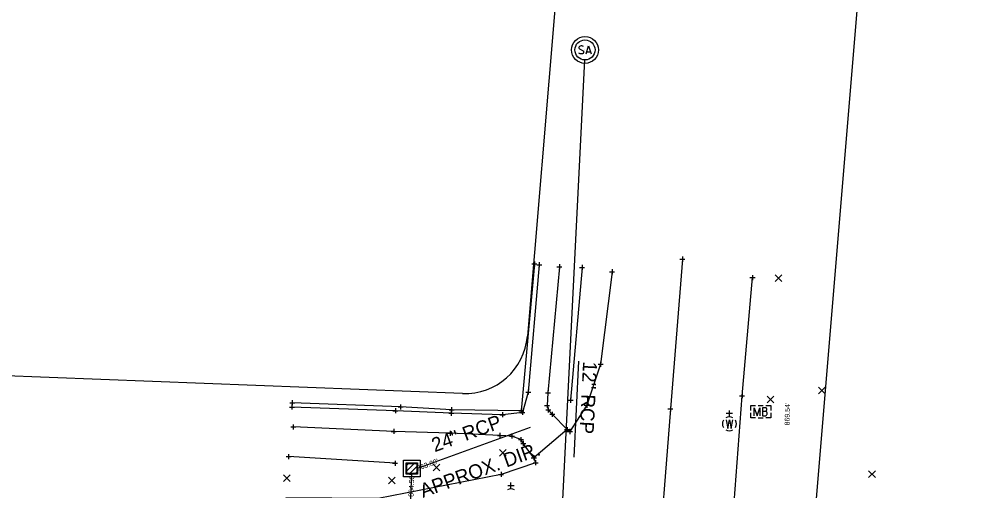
# Model space of a CAD drawing. Extents: x 1380550 to 1381945, y 468927 to 470496.
# Drawn here: x 1381495.3 to 1381685.3, y 470278.1 to 470372 of the extents above; entities that cross this region are included whole.
import ezdxf

# ---------------------------------------------------------------- set-up
doc = ezdxf.new("R2010")
doc.units = 0
for name, color, linetype in [('DR_X_Cells', 7, 'Continuous'), ('DR_X_Ditch', 7, 'Continuous'), ('DR_X_Storm_Sewer', 7, 'Continuous'), ('DR_X_Text', 7, 'Continuous'), ('GK_Drainage_Nodes', 7, 'Continuous'), ('PV_X_COP', 7, 'Continuous'), ('PV_X_EOP', 7, 'Continuous'), ('PV_X_Walk', 7, 'Continuous'), ('RD_X_Cells', 7, 'Continuous'), ('RD_X_Fence', 7, 'Continuous'), ('RW_X_Esmt_General', 7, 'Continuous'), ('SC_Scratch1', 7, 'Continuous'), ('SV_X_Random_Point', 7, 'Continuous'), ('SV_X_Shot_Marker', 7, 'Continuous'), ('UT_X_Sanitary_Cells', 7, 'Continuous'), ('UT_X_Sanitary_Line', 7, 'Continuous'), ('UT_X_Sanitary_Text', 7, 'Continuous'), ('UT_X_Water_Cells', 7, 'Continuous')]:
    doc.layers.add(name, color=color, linetype=linetype)

msp = doc.modelspace()

# ---------------------------------------------------------------- linework, layer by layer
at = {"layer": 'DR_X_Cells'}
for p, q in [((1381572.37, 470281.94), (1381574.13, 470283.7)), ((1381572.37, 470283.07), (1381573, 470283.7)), ((1381572.97, 470281.41), (1381574.66, 470283.1)), ((1381574.1, 470281.41), (1381574.66, 470281.97))]:
    msp.add_line(p, q, dxfattribs=at)
for points in [[(1381571.85, 470284.22), (1381575.18, 470284.22), (1381575.18, 470280.89), (1381571.85, 470280.89)], [(1381572.37, 470283.7), (1381574.66, 470283.7), (1381574.66, 470281.41), (1381572.37, 470281.41)], [(1381572.52, 470283.56), (1381574.51, 470283.56), (1381574.51, 470281.56), (1381572.52, 470281.56)]]:
    msp.add_lwpolyline(points, close=True, dxfattribs=at)
at = {"layer": 'DR_X_Ditch'}
for points in [[(1381607.42, 470322.6), (1381605.14, 470296.15)], [(1381570.18, 470283.61), (1381548.95, 470284.92)]]:
    msp.add_lwpolyline(points, dxfattribs=at)
at = {"layer": 'DR_X_Storm_Sewer'}
for p, q in [((1381574.51, 470282.56), (1381597.14, 470290.77)), ((1381572.17, 470247.58), (1381573.51, 470281.56))]:
    msp.add_line(p, q, dxfattribs=at)
at = {"layer": 'DR_X_Text'}
msp.add_line((1381605.85, 470284.84), (1381606.8, 470303.9), dxfattribs=at)
at = {"layer": 'GK_Drainage_Nodes'}
for p, q in [((1381608, 470367.88), (1381608, 470367.88)), ((1381608, 470365.88), (1381608, 470365.88)), ((1381608, 470365.88), (1381608, 470365.88)), ((1381608, 470365.88), (1381608, 470365.88)), ((1381608, 470363.88), (1381608, 470363.88)), ((1381573.51, 470284.22), (1381573.51, 470284.22)), ((1381572.52, 470282.56), (1381572.52, 470282.56)), ((1381573.51, 470283.56), (1381573.51, 470283.56)), ((1381573.51, 470282.56), (1381573.51, 470282.56)), ((1381573.51, 470282.56), (1381573.51, 470282.56)), ((1381573.51, 470282.56), (1381573.51, 470282.56)), ((1381574.51, 470282.56), (1381574.51, 470282.56)), ((1381573.51, 470281.56), (1381573.51, 470281.56)), ((1381573.51, 470280.89), (1381573.51, 470280.89))]:
    msp.add_line(p, q, dxfattribs=at)
msp.add_circle((1381608, 470365.88), 2, dxfattribs=at)
at = {"layer": 'PV_X_COP'}
msp.add_lwpolyline([(1381627.41, 470324.23), (1381625.02, 470294.42), (1381622.34, 470259.95), (1381618.76, 470220.14), (1381616.92, 470200.19), (1381615.1, 470178.83), (1381610.95, 470124.78), (1381606.49, 470071.23), (1381602.26, 470019.36), (1381598.18, 469969.8), (1381595.01, 469928.06), (1381590.91, 469878.81), (1381589.36, 469859.11), (1381585.99, 469815.58), (1381581.29, 469760.78)], dxfattribs=at)
at = {"layer": 'PV_X_EOP'}
for points in [[(1381613.39, 470321.73), (1381611.1, 470303.3), (1381608.36, 470295.15), (1381605.01, 470289.92), (1381604.44, 470290.29), (1381597.81, 470284.69), (1381598.17, 470283.7), (1381591.29, 470281.39), (1381566.82, 470276.57), (1381548.39, 470276.73)], [(1381677.82, 470243.96), (1381667.49, 470244.25), (1381661.32, 470244.63), (1381647.84, 470248.5), (1381643.91, 470251.15), (1381641.09, 470253.81), (1381638.63, 470258.08), (1381637.55, 470273.11), (1381639.29, 470297.03), (1381641.37, 470320.57)]]:
    msp.add_lwpolyline(points, dxfattribs=at)
at = {"layer": 'PV_X_Walk'}
for points in [[(1381598.9, 470323.13), (1381596.7, 470297.78), (1381595.54, 470293.73), (1381591.57, 470293.27), (1381581.37, 470293.57), (1381570.24, 470294.06), (1381549.62, 470294.77)], [(1381602.92, 470322.73), (1381600.62, 470297.61), (1381600.44, 470295.13), (1381600.68, 470294.22), (1381601.47, 470293.36), (1381604.44, 470290.29), (1381597.81, 470284.69), (1381595.69, 470287.54), (1381595.24, 470288.31), (1381593.46, 470289.01), (1381591.05, 470289.15), (1381581.13, 470289.58), (1381569.91, 470289.93), (1381549.88, 470290.83)]]:
    msp.add_lwpolyline(points, dxfattribs=at)
at = {"layer": 'RD_X_Cells'}
for p, q in [((1381642.49, 470295.09), (1381643.5, 470295.09)), ((1381643.01, 470293.86), (1381643.01, 470293.86)), ((1381642.49, 470292.64), (1381643.5, 470292.64))]:
    msp.add_line(p, q, dxfattribs=at)
for points in [[(1381641.01, 470294.12), (1381641.01, 470295.09), (1381641.98, 470295.09)], [(1381644.01, 470295.09), (1381645.01, 470295.09), (1381645.01, 470294.12)], [(1381641.98, 470292.64), (1381641.01, 470292.64), (1381641.01, 470293.61)], [(1381641.71, 470293.06), (1381641.71, 470294.66), (1381642.29, 470293.06), (1381642.84, 470294.66), (1381642.84, 470293.06)], [(1381644.03, 470293.93), (1381644.09, 470294), (1381644.13, 470294.03), (1381644.15, 470294.07), (1381644.17, 470294.1), (1381644.19, 470294.15), (1381644.2, 470294.19), (1381644.23, 470294.27), (1381644.23, 470294.31), (1381644.23, 470294.36), (1381644.22, 470294.44), (1381644.19, 470294.5), (1381644.15, 470294.55), (1381644.09, 470294.6), (1381644.04, 470294.63), (1381644.02, 470294.64), (1381643.95, 470294.66), (1381643.33, 470294.66), (1381643.33, 470293.06), (1381644.03, 470293.06), (1381644.12, 470293.11), (1381644.19, 470293.18), (1381644.25, 470293.28), (1381644.29, 470293.39), (1381644.3, 470293.51), (1381644.3, 470293.58), (1381644.28, 470293.66), (1381644.23, 470293.77), (1381644.17, 470293.85), (1381644.03, 470293.93), (1381643.33, 470293.93)], [(1381645.01, 470293.61), (1381645.01, 470292.64), (1381644.01, 470292.64)]]:
    msp.add_lwpolyline(points, dxfattribs=at)
at = {"layer": 'RD_X_Fence'}
msp.add_lwpolyline([(1381597.94, 470323.28), (1381595.32, 470294.01), (1381581.44, 470294.24), (1381571.27, 470294.81), (1381549.69, 470295.66)], dxfattribs=at)
at = {"layer": 'RW_X_Esmt_General'}
for p, q in [((1381612.2, 470496.45), (1381596.54, 470308.93)), ((1381583.6, 470297.48), (1380561.01, 470336.99))]:
    msp.add_line(p, q, dxfattribs=at)
msp.add_lwpolyline([(1381668.02, 470443.9), (1381652.43, 470257.4), (1381784.26, 470253.87)], dxfattribs=at)
msp.add_arc((1381584.08, 470309.97), 12.5, 267.7876, 355.2253, dxfattribs=at)
at = {"layer": 'SV_X_Random_Point'}
for p, q in [((1381645.91, 470319.77), (1381647.24, 470321.1)), ((1381645.91, 470321.1), (1381647.24, 470319.77)), ((1381654.52, 470297.42), (1381655.86, 470298.76)), ((1381654.52, 470298.76), (1381655.86, 470297.42)), ((1381644.26, 470295.6), (1381645.6, 470296.93)), ((1381644.26, 470296.93), (1381645.6, 470295.6)), ((1381590.99, 470284.99), (1381592.32, 470286.32)), ((1381590.99, 470286.32), (1381592.32, 470284.99)), ((1381577.75, 470282.09), (1381579.09, 470283.42)), ((1381577.75, 470283.42), (1381579.09, 470282.09)), ((1381664.51, 470280.76), (1381665.85, 470282.1)), ((1381664.51, 470282.1), (1381665.85, 470280.76)), ((1381547.97, 470279.98), (1381549.3, 470281.31)), ((1381547.97, 470281.31), (1381549.3, 470279.98)), ((1381568.86, 470279.49), (1381570.2, 470280.83)), ((1381568.86, 470280.83), (1381570.2, 470279.49))]:
    msp.add_line(p, q, dxfattribs=at)
at = {"layer": 'SV_X_Shot_Marker'}
for p, q in [((1381597.94, 470323.78), (1381597.94, 470322.78)), ((1381598.9, 470323.63), (1381598.9, 470322.63)), ((1381626.91, 470324.23), (1381627.91, 470324.23)), ((1381627.41, 470324.73), (1381627.41, 470323.73)), ((1381627.41, 470324.23), (1381627.41, 470324.23)), ((1381597.44, 470323.28), (1381598.44, 470323.28)), ((1381597.94, 470323.28), (1381597.94, 470323.28)), ((1381598.4, 470323.13), (1381599.4, 470323.13)), ((1381598.9, 470323.13), (1381598.9, 470323.13)), ((1381602.42, 470322.73), (1381603.42, 470322.73)), ((1381602.92, 470323.23), (1381602.92, 470322.23)), ((1381602.92, 470322.73), (1381602.92, 470322.73)), ((1381606.92, 470322.6), (1381607.92, 470322.6)), ((1381607.42, 470323.1), (1381607.42, 470322.1)), ((1381607.42, 470322.6), (1381607.42, 470322.6)), ((1381612.89, 470321.73), (1381613.89, 470321.73)), ((1381613.39, 470322.23), (1381613.39, 470321.23)), ((1381613.39, 470321.73), (1381613.39, 470321.73)), ((1381640.87, 470320.57), (1381641.87, 470320.57)), ((1381641.37, 470321.07), (1381641.37, 470320.07)), ((1381641.37, 470320.57), (1381641.37, 470320.57)), ((1381610.6, 470303.3), (1381611.6, 470303.3)), ((1381610.6, 470303.3), (1381611.6, 470303.3)), ((1381611.1, 470303.8), (1381611.1, 470302.8)), ((1381611.1, 470303.8), (1381611.1, 470302.8)), ((1381611.1, 470303.3), (1381611.1, 470303.3)), ((1381611.1, 470303.3), (1381611.1, 470303.3)), ((1381596.2, 470297.78), (1381597.2, 470297.78)), ((1381596.2, 470297.78), (1381597.2, 470297.78)), ((1381596.7, 470298.28), (1381596.7, 470297.28)), ((1381596.7, 470298.28), (1381596.7, 470297.28)), ((1381596.7, 470297.78), (1381596.7, 470297.78)), ((1381596.7, 470297.78), (1381596.7, 470297.78)), ((1381600.12, 470297.61), (1381601.12, 470297.61)), ((1381600.62, 470298.11), (1381600.62, 470297.11)), ((1381600.62, 470297.61), (1381600.62, 470297.61)), ((1381638.79, 470297.03), (1381639.79, 470297.03)), ((1381639.29, 470297.53), (1381639.29, 470296.53)), ((1381639.29, 470297.03), (1381639.29, 470297.03)), ((1381549.19, 470295.66), (1381550.19, 470295.66)), ((1381549.62, 470295.27), (1381549.62, 470294.27)), ((1381549.69, 470296.16), (1381549.69, 470295.16)), ((1381549.69, 470295.66), (1381549.69, 470295.66)), ((1381571.27, 470295.31), (1381571.27, 470294.31)), ((1381599.94, 470295.13), (1381600.94, 470295.13)), ((1381599.94, 470295.13), (1381600.94, 470295.13)), ((1381600.44, 470295.63), (1381600.44, 470294.63)), ((1381600.44, 470295.63), (1381600.44, 470294.63)), ((1381600.44, 470295.13), (1381600.44, 470295.13)), ((1381600.44, 470295.13), (1381600.44, 470295.13)), ((1381604.64, 470296.15), (1381605.64, 470296.15)), ((1381605.14, 470296.65), (1381605.14, 470295.65)), ((1381605.14, 470296.15), (1381605.14, 470296.15)), ((1381607.86, 470295.15), (1381608.86, 470295.15)), ((1381608.36, 470295.65), (1381608.36, 470294.65)), ((1381608.36, 470295.15), (1381608.36, 470295.15)), ((1381549.12, 470294.77), (1381550.12, 470294.77)), ((1381549.62, 470294.77), (1381549.62, 470294.77)), ((1381569.74, 470294.06), (1381570.74, 470294.06)), ((1381570.24, 470294.56), (1381570.24, 470293.56)), ((1381570.24, 470294.06), (1381570.24, 470294.06)), ((1381570.77, 470294.81), (1381571.77, 470294.81)), ((1381571.27, 470294.81), (1381571.27, 470294.81)), ((1381580.87, 470293.57), (1381581.87, 470293.57)), ((1381580.94, 470294.24), (1381581.94, 470294.24)), ((1381581.37, 470294.07), (1381581.37, 470293.07)), ((1381581.37, 470293.57), (1381581.37, 470293.57)), ((1381581.44, 470294.74), (1381581.44, 470293.74)), ((1381581.44, 470294.24), (1381581.44, 470294.24)), ((1381591.07, 470293.27), (1381592.07, 470293.27)), ((1381591.07, 470293.27), (1381592.07, 470293.27)), ((1381591.57, 470293.77), (1381591.57, 470292.77)), ((1381591.57, 470293.77), (1381591.57, 470292.77)), ((1381591.57, 470293.27), (1381591.57, 470293.27)), ((1381591.57, 470293.27), (1381591.57, 470293.27)), ((1381594.82, 470294.01), (1381595.82, 470294.01)), ((1381595.04, 470293.73), (1381596.04, 470293.73)), ((1381595.32, 470294.51), (1381595.32, 470293.51)), ((1381595.32, 470294.01), (1381595.32, 470294.01)), ((1381595.54, 470294.23), (1381595.54, 470293.23)), ((1381595.54, 470293.73), (1381595.54, 470293.73)), ((1381600.18, 470294.22), (1381601.18, 470294.22)), ((1381600.68, 470294.72), (1381600.68, 470293.72)), ((1381600.68, 470294.22), (1381600.68, 470294.22)), ((1381600.97, 470293.36), (1381601.97, 470293.36)), ((1381600.97, 470293.36), (1381601.97, 470293.36)), ((1381601.47, 470293.86), (1381601.47, 470292.86)), ((1381601.47, 470293.86), (1381601.47, 470292.86)), ((1381601.47, 470293.36), (1381601.47, 470293.36)), ((1381601.47, 470293.36), (1381601.47, 470293.36)), ((1381624.52, 470294.42), (1381625.52, 470294.42)), ((1381625.02, 470294.92), (1381625.02, 470293.92)), ((1381625.02, 470294.42), (1381625.02, 470294.42)), ((1381549.88, 470291.33), (1381549.88, 470290.33)), ((1381549.38, 470290.83), (1381550.38, 470290.83)), ((1381549.88, 470290.83), (1381549.88, 470290.83)), ((1381569.41, 470289.93), (1381570.41, 470289.93)), ((1381569.91, 470290.43), (1381569.91, 470289.43)), ((1381569.91, 470289.93), (1381569.91, 470289.93)), ((1381580.63, 470289.58), (1381581.63, 470289.58)), ((1381581.13, 470290.08), (1381581.13, 470289.08)), ((1381581.13, 470289.58), (1381581.13, 470289.58)), ((1381591.05, 470289.65), (1381591.05, 470288.65)), ((1381593.46, 470289.51), (1381593.46, 470288.51)), ((1381593.46, 470289.51), (1381593.46, 470288.51)), ((1381603.94, 470290.29), (1381604.94, 470290.29)), ((1381603.94, 470290.29), (1381604.94, 470290.29)), ((1381604.44, 470290.79), (1381604.44, 470289.79)), ((1381604.44, 470290.79), (1381604.44, 470289.79)), ((1381604.44, 470290.29), (1381604.44, 470290.29)), ((1381604.44, 470290.29), (1381604.44, 470290.29)), ((1381604.51, 470289.92), (1381605.51, 470289.92)), ((1381604.51, 470289.92), (1381605.51, 470289.92)), ((1381605.01, 470290.42), (1381605.01, 470289.42)), ((1381605.01, 470290.42), (1381605.01, 470289.42)), ((1381605.01, 470289.92), (1381605.01, 470289.92)), ((1381605.01, 470289.92), (1381605.01, 470289.92)), ((1381590.55, 470289.15), (1381591.55, 470289.15)), ((1381591.05, 470289.15), (1381591.05, 470289.15)), ((1381592.96, 470289.01), (1381593.96, 470289.01)), ((1381592.96, 470289.01), (1381593.96, 470289.01)), ((1381593.46, 470289.01), (1381593.46, 470289.01)), ((1381593.46, 470289.01), (1381593.46, 470289.01)), ((1381594.74, 470288.31), (1381595.74, 470288.31)), ((1381595.19, 470287.54), (1381596.19, 470287.54)), ((1381595.19, 470287.54), (1381596.19, 470287.54)), ((1381595.24, 470288.81), (1381595.24, 470287.81)), ((1381595.24, 470288.31), (1381595.24, 470288.31)), ((1381595.69, 470288.04), (1381595.69, 470287.04)), ((1381595.69, 470288.04), (1381595.69, 470287.04)), ((1381595.69, 470287.54), (1381595.69, 470287.54)), ((1381595.69, 470287.54), (1381595.69, 470287.54)), ((1381548.45, 470284.92), (1381549.45, 470284.92)), ((1381548.95, 470285.42), (1381548.95, 470284.42)), ((1381548.95, 470284.92), (1381548.95, 470284.92)), ((1381570.18, 470284.11), (1381570.18, 470283.11)), ((1381597.31, 470284.69), (1381598.31, 470284.69)), ((1381597.31, 470284.69), (1381598.31, 470284.69)), ((1381597.67, 470283.7), (1381598.67, 470283.7)), ((1381597.81, 470285.19), (1381597.81, 470284.19)), ((1381597.81, 470285.19), (1381597.81, 470284.19)), ((1381597.81, 470284.69), (1381597.81, 470284.69)), ((1381597.81, 470284.69), (1381597.81, 470284.69)), ((1381598.17, 470284.2), (1381598.17, 470283.2)), ((1381598.17, 470283.7), (1381598.17, 470283.7)), ((1381569.68, 470283.61), (1381570.68, 470283.61)), ((1381570.18, 470283.61), (1381570.18, 470283.61)), ((1381591.29, 470281.89), (1381591.29, 470280.89)), ((1381590.79, 470281.39), (1381591.79, 470281.39)), ((1381591.29, 470281.39), (1381591.29, 470281.39))]:
    msp.add_line(p, q, dxfattribs=at)
at = {"layer": 'UT_X_Sanitary_Cells'}
for points in [[(1381607.67, 470366.57), (1381607.64, 470366.59), (1381607.61, 470366.62), (1381607.49, 470366.66), (1381607.35, 470366.68), (1381607.25, 470366.68), (1381607.22, 470366.68), (1381607.05, 470366.65), (1381606.91, 470366.57), (1381606.83, 470366.47), (1381606.8, 470366.37), (1381606.8, 470366.29), (1381606.83, 470366.19), (1381606.93, 470366.1), (1381607.62, 470365.73), (1381607.68, 470365.68), (1381607.71, 470365.62), (1381607.73, 470365.55), (1381607.73, 470365.47), (1381607.72, 470365.4), (1381607.71, 470365.35), (1381607.68, 470365.28), (1381607.66, 470365.23), (1381607.63, 470365.2), (1381607.59, 470365.16), (1381607.56, 470365.13), (1381607.51, 470365.11), (1381607.47, 470365.1), (1381607.35, 470365.08), (1381607.18, 470365.08), (1381607.06, 470365.11), (1381606.9, 470365.2), (1381606.8, 470365.27)], [(1381608.21, 470365.08), (1381608.71, 470366.68), (1381609.21, 470365.08)], [(1381609.08, 470365.46), (1381608.34, 470365.46)]]:
    msp.add_lwpolyline(points, dxfattribs=at)
for radius in [2.67, 2]:
    msp.add_circle((1381608, 470365.88), radius, dxfattribs=at)
at = {"layer": 'UT_X_Sanitary_Line'}
msp.add_line((1381607.9, 470363.89), (1381601.16, 470229.04), dxfattribs=at)
at = {"layer": 'UT_X_Sanitary_Text'}
msp.add_line((1381605.85, 470284.84), (1381606.8, 470303.9), dxfattribs=at)
at = {"layer": 'UT_X_Water_Cells'}
for p, q in [((1381637.41, 470293.49), (1381636.14, 470293.49)), ((1381636.78, 470292.85), (1381636.78, 470294.12)), ((1381636.78, 470291.45), (1381636.78, 470291.45)), ((1381593.9, 470279.11), (1381592.63, 470279.11)), ((1381593.26, 470278.48), (1381593.26, 470279.75))]:
    msp.add_line(p, q, dxfattribs=at)
msp.add_lwpolyline([(1381636.14, 470292.27), (1381636.46, 470290.55), (1381636.78, 470292.27), (1381637.1, 470290.55), (1381637.42, 470292.27)], dxfattribs=at)
for centre, start, end in [((1381636.78, 470291.45), 150.0184, 209.9816), ((1381636.78, 470291.45), 60.0184, 120.0157), ((1381636.78, 470291.45), 330.0184, 29.9816), ((1381636.78, 470291.45), 239.9843, 299.9816), ((1381593.26, 470277.08), 60.0184, 120.0157)]:
    msp.add_arc(centre, 1.4, start, end, dxfattribs=at)

# ---------------------------------------------------------------- texts
at = {"layer": 'DR_X_Text'}
for s, rotation, p in [('12" RCP', 267.1364, (1381607.63, 470303.92)), ('24" RCP', 19.9584, (1381578.06, 470285.78)), ('APPROX. DIR.', 19.9584, (1381575.73, 470276.7))]:
    msp.add_text(s, height=2.8, rotation=rotation, dxfattribs=at).set_placement(p)
at = {"layer": 'SC_Scratch1'}
for s, rotation, p in [("869.54'", 89.082, (1381648.77, 470291.13)), ("863.89'", 19.9584, (1381574.69, 470282.09)), ("864.50'", 87.7266, (1381573.83, 470276.91))]:
    msp.add_text(s, height=1, rotation=rotation, dxfattribs=at).set_placement(p)
at = {"layer": 'UT_X_Sanitary_Text'}
msp.add_text('12" RCP', height=2.8, rotation=267.1364, dxfattribs=at).set_placement((1381607.63, 470303.92))

doc.saveas('drawing.dxf')
